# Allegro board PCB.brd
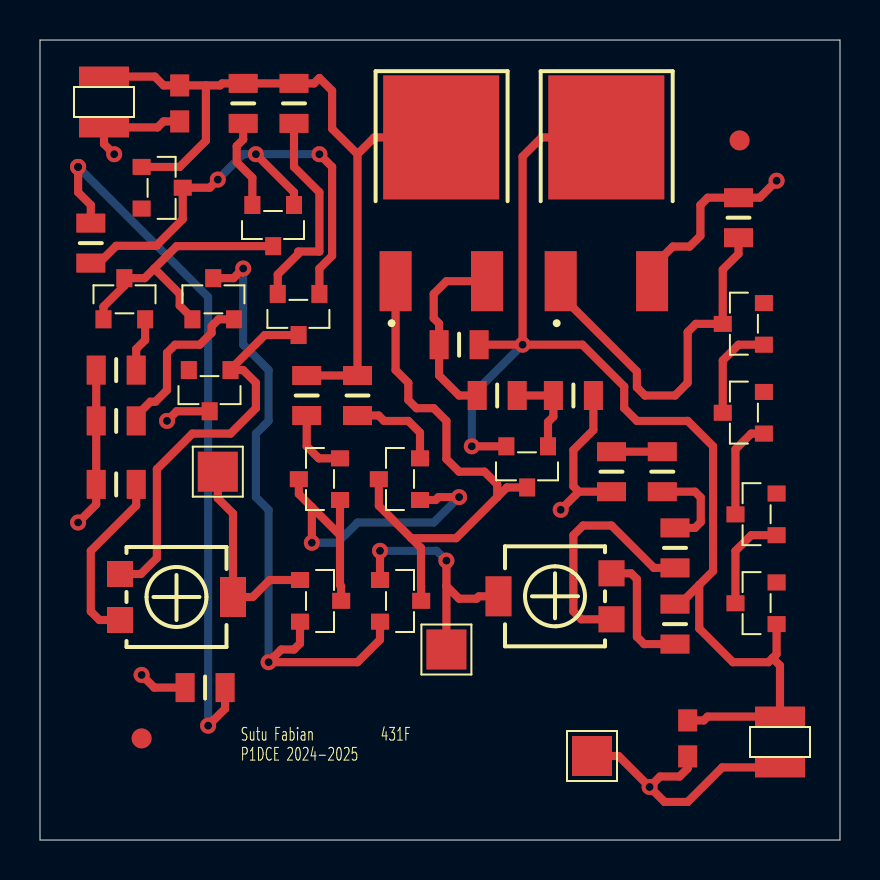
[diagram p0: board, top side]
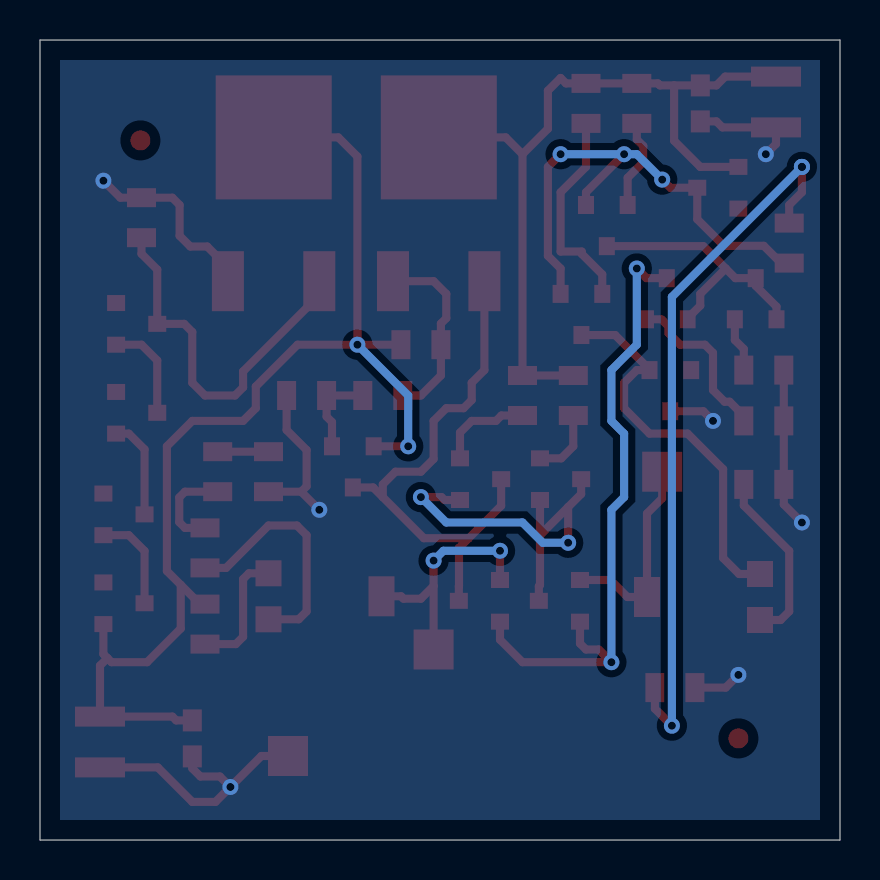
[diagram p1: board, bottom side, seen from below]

Outline 40 x 40 mm; copper layers: TOP, BOTTOM. Coordinates in mm from the lower left corner of the outline.
Outline path: 0,40 40,40 40,0 0,0 0,40

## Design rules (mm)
constraint set DEFAULT: min track width 0.406

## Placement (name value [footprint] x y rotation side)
C1  10u  [CAPC2008X126N_0805]  6.99 36.83 90 top
COUT  10u  [CAPC2008X126N_0805]  32.38 5.08 90 top
D1  BZX84-C10  [TO236AA]  5.08 33.66 180 top
D2  BZX84-C6V8  [TO236AA]  9.53 23.5 90 top
D3  BZX84-C10  [TO236AA]  36.83 10.79 0 top
D4  BZX84-C10  [TO236AA]  36.83 15.24 0 top
D5  BZX84-C10  [TO236AA]  36.2 20.32 0 top
D6  BZX84-C6V2  [TO236AA]  36.2 24.77 0 top
GND  TEST POINT  [PAD_2X2]  27.6 4.2 0 top
NOREF  -  [unnamed]  34.98 34.98 0 top
NOREF#2  -  [unnamed]  5.08 5.08 0 top
P1  2k  [TS53YL]  4 11 180 top
P2  2k  [TS53YL]  28.57 13.34 0 top
Q1  QBC817-25  [TO236AA]  12.7 31.75 90 top
Q2  QBC817-25  [TO236AA]  13.97 27.3 90 top
Q3  QBC807-25  [TO236AA]  3.17 26.04 270 top
Q4  QBC807-25  [TO236AA]  7.62 26.04 270 top
Q5  QBC807-25  [TO236AA]  13 13 180 top
Q6  QBC807-25  [TO236AA]  17 13 180 top
Q7  QBC817-25  [TO236AA]  15 17 0 top
Q8  QBC817-25  [TO236AA]  19 17 0 top
Q9  QMJD32CT4G  [DPACK]  17.78 27.94 0 top
Q10  QBC807-25  [TO236AA]  25.4 19.68 90 top
Q11  QMJD32CT4G  [DPACK]  26.04 27.94 0 top
R1  2.7k  [RES2012X50N_0805]  2.54 29.84 270 top
R2  9.1k  [RES2012X50N_0805]  10.16 36.83 90 top
R3  1.5k  [RES2012X50N_0805]  12.7 36.83 90 top
R4  220k  [RES2012X50N_0805]  3.81 17.78 0 top
R5  100  [RES2012X50N_0805]  3.81 23.5 0 top
R6  100  [RES2012X50N_0805]  3.81 20.95 0 top
R7  100  [RES2012X50N_0805]  13.34 22.23 90 top
R8  100  [RES2012X50N_0805]  15.88 22.23 90 top
R9  33  [RES2012X50N_0805]  20.95 24.77 0 top
R10  1.5k  [RES2012X50N_0805]  22.86 22.23 180 top
R11  47k  [RES2012X50N_0805]  26.67 22.23 180 top
R12  100k  [RES2012X50N_0805]  31.75 10.79 90 top
R13  3.3k  [RES2012X50N_0805]  31.75 14.61 270 top
R14  9.1k  [RES2012X50N_0805]  31.11 18.41 270 top
R15  15k  [RES2012X50N_0805]  28.57 18.41 90 top
R16  1k  [RES2012X50N_0805]  34.92 31.11 270 top
R18  2k  [RES2012X50N_0805]  8.26 7.62 0 top
TP1  TEST POINT  [PAD_2X2]  20.32 9.53 0 top
TP2  TEST POINT  [PAD_2X2]  8.89 18.41 0 top
VIN  CON2  [CONECTOR]  3.2 36.9 0 top
VOUT  CON2  [CONECTOR]  37 4.9 0 top

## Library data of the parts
C1 COUT = C
D1 D3-D5 = BZX84-C10_4
D2 = BZX84-C6V8_3
D6 = BZX84-C6V2_4
GND TP1 TP2 = TEST POINT
P1 P2 = POT
Q1 Q2 Q7 Q8 = QBC817-25_0
Q3-Q6 Q10 = QBC807-25_0
Q9 Q11 = QMJD32CT4G_0
R1-R16 R18 = R
VIN = CON2_2
VOUT = CON2

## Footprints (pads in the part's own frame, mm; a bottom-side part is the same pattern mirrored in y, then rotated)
CAPC2008X126N_0805
  rect 1.1x0.95 smd: 1(-0.9,0) 2(0.9,0)
CONECTOR
  rect 2.5x1 smd: 1(0,1.27) 2(0,-1.27)
DPACK
  rect 1.6x3 smd: 1(0,0) 3(4.57,0)
  rect 5.8x6.2 smd: 2(2.28,7.19)
PAD_2X2
  rect 2x2 smd: 1(0,0)
RES2012X50N_0805
  rect 0.95x1.45 smd: 1(-1,0) 2(1,0)
TO236AA
  rect 0.9x0.8 smd: 1(0,0) 2(0,2.083) 3(-2.057,1.041)
TS53YL
  rect 1.3x1.3 smd: 1(0,0) 3(0,-2.3)
  rect 1.3x2 smd: 2(-5.65,-1.15)
unnamed
  round 1 smd: (0,0)

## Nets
0: C1.1 COUT.1 D2.3 GND.1 Q11.3(E) R4.1 R5.1 R6.1 R11.1 R15.1 R16.1 R18.1 VIN.2 VOUT.2
N29620: C1.2 D1.1 Q9.2 R2.2 R3.2 R7.2 R8.2 VIN.1(2)
N29692: Q4.3 Q5.2(E) Q6.2(E)
N29698: Q5.3 Q7.1 Q7.3 Q8.1
N29704: Q6.3 Q8.3 Q9.1 Q10.3
N29750: Q8.2(E) R8.1
N29762: Q7.2(E) R7.1
N29826: Q9.3(E) R9.1 R10.2
N29912: COUT.2 D3.1 Q10.2(E) Q11.2 R9.2 R12.2 VOUT.1
N29916: Q10.1 R10.1 R11.2
N30052: P2.3 R13.2
N30094: D2.1 P1.3 Q2.3
N30376: D3.3 D4.1
N30382: D4.3 D5.1
N30508: D6.3 Q11.1 R16.2
N30716: Q1.3 Q3.1 Q3.3 Q4.1
N35325: R13.1 R14.2
N36428: P2.1 R12.1
N39990: D1.3 Q1.1 Q2.1 R1.2
N42166: D5.3 D6.1
N48107: P1.1 R4.2
N55403: P1.2(T) Q5.1 TP2.1
N55487: P2.2(T) Q6.1 TP1.1
N73496: Q2.2(E) R3.1
N81296: R1.1 R18.2
N307701: Q4.2(E) R6.2
N307961: Q3.2(E) R5.2
N399761: Q1.2(E) R2.1
N589880: R14.1 R15.2

Pads without a net: D1 2; D2 2; D3 2; D4 2; D5 2; D6 2

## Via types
v1: diameter 0.8, hole 0.4, TOP to BOTTOM, 21 vias

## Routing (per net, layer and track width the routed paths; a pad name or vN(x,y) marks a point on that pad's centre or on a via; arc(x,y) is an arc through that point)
0: length 50.1
  TOP w0.406: v1(36.83,32.96) 35.98,32.12 33.38,32.12 33.02,31.75 33.02,30.21 32.48,29.67 31.64,29.67 30.61,28.64 Q11.3 ; R11.1 27.67,20.5 26.67,19.5 26.67,17.68 26.94,17.41 ; 26.94,17.41 v1(26.04,16.51) ; 26.94,17.41 R15.1 ; v1(5.08,8.26) 5.71,7.62 R18.1 ; R5.1 R6.1 R4.1 2.81,16.78 v1(1.91,15.88) ; C1.1 6.18,35.93 5.88,35.63 VIN.2 3.2,34.8 v1(3.71,34.29) ; VOUT.2 34.11,3.63 32.38,1.91 31.23,1.91 v1(30.48,2.65) ; v1(6.35,20.95) 6.83,21.44 D2.3 ; v1(30.48,2.65) 28.93,4.2 GND.1 ; v1(30.48,2.65) 31,3.17 31.98,3.17 32.38,3.58 COUT.1
N29620: length 40.4
  TOP w0.406: 15.88,34.29 16.71,35.13 Q9.2 ; 15.88,34.29 R8.2 R7.2 ; 15.88,34.29 14.61,35.56 14.61,37.47 13.97,38.1 13.7,37.83 R3.2 R2.2 9.1,37.83 9,37.73 8.29,37.73 ; 8.29,37.73 8.29,34.96 6.99,33.66 D1.1 ; 8.29,37.73 C1.2 6.18,37.73 5.74,38.17 VIN.1
N29692: length 32.4
  TOP w0.406: v1(10.16,28.57) 9.68,28.09 Q4.3 ; Q5.2 13,9.82 12.7,9.53 12.06,9.53 v1(11.43,8.89) 15.88,8.89 17,10.02 Q6.2
  BOTTOM w0.406: v1(11.43,8.89) 11.43,16.51 10.79,17.14 10.79,20.32 11.43,20.95 11.43,23.5 10.16,24.77 v1(10.16,28.57)
N29698: length 20.8
  TOP w0.406: Q7.1 15,15.24 ; 15,15.24 15,12.75 15.06,12.69 Q5.3 ; 15,15.24 13.59,16.65 ; Q8.1 19.78,17 19.93,17.14 v1(20.95,17.14) ; 13.59,16.65 v1(13.59,14.86) ; 13.59,16.65 12.94,17.3 Q7.3
  BOTTOM w0.406: v1(20.95,17.14) 19.68,15.88 15.88,15.88 14.86,14.86 v1(13.59,14.86)
N29704: length 28
  TOP w0.406: Q10.3 23.34,17.63 22.86,17.14 ; 22.86,17.14 22.86,17.78 22.23,18.41 20.95,18.41 20.32,19.05 20.32,20.95 19.68,21.59 18.82,21.59 18.41,22 18.41,22.86 17.78,23.5 Q9.1 ; 22.86,17.14 20.81,15.09 18.56,15.09 ; Q8.3 16.94,16.71 18.56,15.09 ; 18.56,15.09 19.05,14.61 19.05,12.7 19.06,12.69 Q6.3
N29750: length 4.8
  TOP w0.406: Q8.2 19,20.37 18.41,20.95 17.2,20.95 16.93,21.23 R8.1
N29762: length 3.5
  TOP w0.406: Q7.2 13.94,19.08 13.34,19.68 R7.1
N29826: length 9.4
  TOP w0.406: Q9.3 20.32,27.94 19.68,27.3 19.68,26.09 19.95,25.82 R9.1 19.95,23.23 20.95,22.23 R10.2
N29912: length 61.3
  TOP w0.406: Q10.2 v1(21.59,19.68) ; 36.63,9.09 37,8.72 VOUT.1 33.38,6.17 33.19,5.98 COUT.2 ; 36.63,9.09 36.83,9.3 D3.1 ; 36.63,9.09 36.42,8.89 34.65,8.89 32.96,10.57 32.96,12.76 ; 32.96,12.76 33.66,13.45 33.66,19.68 32.38,20.95 29.84,20.95 29.21,21.59 29.21,22.68 27.12,24.77 v1(24.13,24.77) ; 32.96,12.76 32,11.79 R12.2 ; v1(24.13,24.77) R9.2 ; v1(24.13,24.77) 24.13,34.18 25.08,35.13 Q11.2
  BOTTOM w0.406: v1(24.13,24.77) 21.59,22.23 v1(21.59,19.68)
N29916: length 4.5
  TOP w0.406: R10.1 R11.2 25.67,21.17 25.4,20.9 Q10.1
N30052: length 12
  TOP w0.406: P2.3 27.07,11.04 26.67,11.43 26.67,15.24 27.15,15.72 28.57,15.72 30.69,13.61 R13.2
N30094: length 19.8
  TOP w0.406: P1.3 5.04,13.3 5.84,14.1 5.84,18.54 7.62,20.32 9.53,20.32 10.79,21.59 10.79,22.86 10.16,23.5 D2.1 9.53,23.53 11.24,25.25 Q2.3
N30376: length 5
  TOP w0.406: D4.1 35.56,15.24 34.77,14.45 D3.3
N30382: length 5
  TOP w0.406: D5.1 35.56,20.32 34.77,19.53 D4.3
N30508: length 19
  TOP w0.406: Q11.1 26.04,27.24 29.84,23.43 29.84,22.63 30.25,22.23 31.75,22.23 32.38,22.86 32.38,25.4 32.79,25.81 D6.3 34.14,28.52 34.92,29.31 R16.2
N30716: length 13.9
  TOP w0.406: Q3.1 3.17,26.67 4.22,27.71 Q3.3 5.23,28.09 5.72,28.58 ; 5.72,28.58 6.83,29.69 Q1.3 ; 5.72,28.58 6.99,27.3 6.99,26.72 7.62,26.09 Q4.1
N35325: length 4.7
  TOP w0.406: R14.2 32.75,17.41 33.04,17.13 33.04,15.89 32.75,15.61 R13.1
N36428: length 6.3
  TOP w0.406: R12.1 30.21,9.79 29.84,10.16 29.84,13.05 29.56,13.34 P2.1
N39990: length 25.4
  TOP w0.406: R1.2 2.95,28.84 3.81,29.71 5.81,29.71 7.14,31.04 D1.3 8.48,32.61 v1(8.89,33.02) ; v1(10.79,34.29) 12.7,32.38 Q1.1 ; v1(13.97,34.29) 14.61,33.66 14.61,29.21 13.97,28.57 Q2.1
  BOTTOM w0.406: v1(13.97,34.29) v1(10.79,34.29) 10.16,34.29 v1(8.89,33.02)
N42166: length 5
  TOP w0.406: D5.3 34.14,23.98 34.92,24.77 D6.1
N48107: length 8.9
  TOP w0.406: R4.2 4.81,16.72 2.54,14.45 2.54,11.43 2.97,11 P1.1
N55403: length 10.3
  TOP w0.406: Q5.1 11.48,13 10.63,12.15 P1.2 9.65,16.32 8.89,17.08 TP2.1
N55487: length 12.3
  TOP w0.406: Q6.1 v1(17,14.46) ; 20.32,12.7 20.95,12.06 21.82,12.06 21.94,12.19 P2.2 ; 20.32,12.7 v1(20.32,13.97) ; 20.32,12.7 TP1.1
  BOTTOM w0.406: v1(20.32,13.97) 19.83,14.46 v1(17,14.46)
N73496: length 10.5
  TOP w0.406: R3.1 12.7,33.66 13.97,32.38 13.97,29.42 12.91,29.42 12.91,29.31 11.89,28.28 Q2.2
N81296: length 36
  TOP w0.406: v1(1.91,33.66) 1.91,32.38 2.54,31.75 R1.1 ; v1(8.41,5.71) 9.26,6.56 R18.2
  BOTTOM w0.406: v1(1.91,33.66) 8.41,27.15 v1(8.41,5.71)
N307701: length 8.4
  TOP w0.406: R6.2 4.81,21.21 5.52,21.91 5.77,21.91 6.35,22.5 6.35,24.36 6.76,24.77 7.99,24.77 8.58,25.35 8.58,25.69 8.93,26.04 Q4.2
N307961: length 2.7
  TOP w0.406: Q3.2 5.26,25 4.81,24.55 R5.2
N399761: length 4.5
  TOP w0.406: R2.1 10.16,35.02 9.84,34.7 9.84,33.89 10.62,33.11 Q1.2
N589880: length 2.5
  TOP w0.406: R15.2 R14.1

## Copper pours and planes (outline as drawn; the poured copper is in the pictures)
0 on BOTTOM: 1,1 1,39 39,39 39,1

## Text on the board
Ref Des/Silkscreen Top: Sutu Fabian | P1DCE 2024-2025 | 431F
